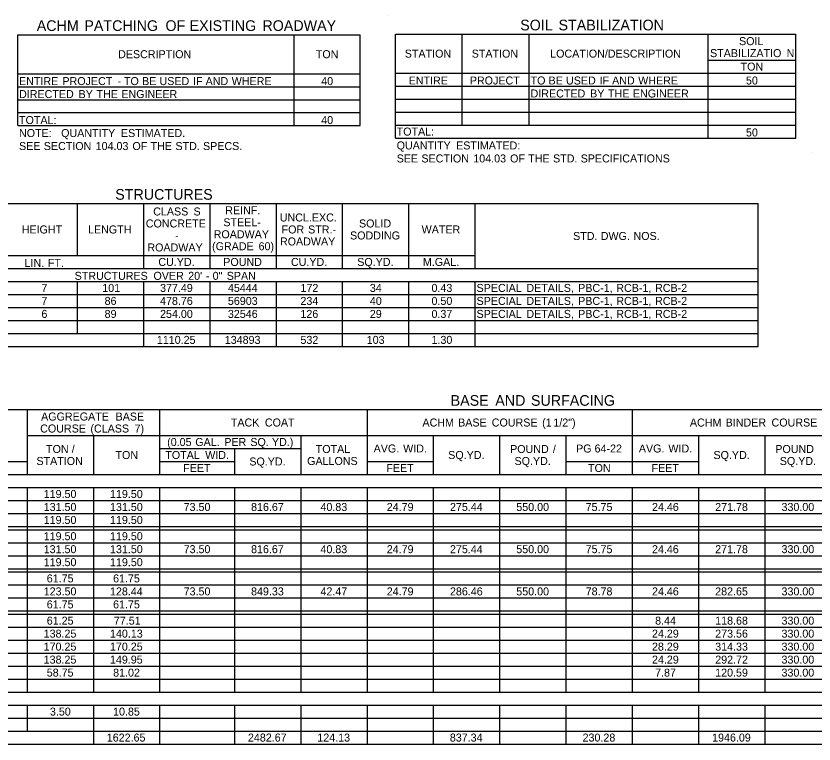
# Model space of a CAD drawing. Extents: x 1955554 to 1962042, y 565952 to 568347.
# Drawn here: x 1959025 to 1959623, y 566455 to 567002 of the extents above; entities that cross this region are included whole.
import ezdxf

# ---------------------------------------------------------------- set-up
doc = ezdxf.new("R2010")
doc.units = 0
doc.layers.add('Default', color=7, linetype='Continuous')

msp = doc.modelspace()

# ---------------------------------------------------------------- linework, layer by layer
at = {"layer": 'Default'}
for p, q in [((1959303.28, 567001.67), (1959303.28, 567001.67)), ((1959025.93, 566987.58), (1959282.84, 566987.58)), ((1959025.93, 566919.33), (1959025.93, 566987.58)), ((1959025.93, 566919.33), (1959025.93, 566987.58)), ((1959233.11, 566919.33), (1959233.11, 566987.58)), ((1959282.84, 566919.33), (1959282.84, 566987.58)), ((1959309.13, 566988.02), (1959609.43, 566988.02)), ((1959309.13, 566910.02), (1959309.13, 566988.02)), ((1959309.13, 566910.02), (1959309.13, 566988.02)), ((1959359.34, 566919.77), (1959359.34, 566988.02)), ((1959409.55, 566919.77), (1959409.55, 566988.02)), ((1959543.61, 566910.02), (1959543.61, 566988.02)), ((1959609.43, 566910.02), (1959609.43, 566988.02)), ((1959609.43, 566910.02), (1959609.43, 566988.02)), ((1959543.61, 566968.52), (1959609.43, 566968.52)), ((1959543.61, 566968.52), (1959609.43, 566968.52)), ((1959025.93, 566958.33), (1959282.84, 566958.33)), ((1959233.11, 566919.33), (1959233.11, 566958.33)), ((1959282.84, 566919.33), (1959282.84, 566958.33)), ((1959309.13, 566958.77), (1959609.43, 566958.77)), ((1959359.34, 566919.77), (1959359.34, 566958.77)), ((1959409.55, 566919.77), (1959409.55, 566958.77)), ((1959543.61, 566919.77), (1959543.61, 566958.77)), ((1959025.93, 566948.58), (1959282.84, 566948.58)), ((1959309.13, 566949.02), (1959609.43, 566949.02)), ((1959543.61, 566949.02), (1959609.43, 566949.02)), ((1959025.93, 566938.83), (1959282.84, 566938.83)), ((1959309.13, 566939.27), (1959609.43, 566939.27)), ((1959025.93, 566929.08), (1959282.84, 566929.08)), ((1959309.13, 566929.52), (1959609.43, 566929.52)), ((1959025.93, 566919.33), (1959282.84, 566919.33)), ((1959309.13, 566919.77), (1959609.43, 566919.77)), ((1959309.13, 566919.77), (1959609.43, 566919.77)), ((1959309.13, 566910.02), (1959609.43, 566910.02)), ((1959621.57, 566899.1), (1959621.57, 566899.1)), ((1958692.87, 566860.92), (1959581.1, 566860.92)), ((1959070.69, 566821.92), (1959070.69, 566860.92)), ((1959120.41, 566812.17), (1959120.41, 566860.92)), ((1959170.14, 566812.17), (1959170.14, 566860.92)), ((1959219.86, 566812.17), (1959219.86, 566860.92)), ((1959269.59, 566812.17), (1959269.59, 566860.92)), ((1959319.31, 566812.17), (1959319.31, 566860.92)), ((1959319.31, 566812.17), (1959319.31, 566860.92)), ((1959369.04, 566812.17), (1959369.04, 566860.92)), ((1959581.1, 566753.67), (1959581.1, 566860.92)), ((1958971.24, 566821.92), (1959369.04, 566821.92)), ((1959170.14, 566812.17), (1959170.14, 566821.92)), ((1959219.86, 566812.17), (1959219.86, 566821.92)), ((1959269.59, 566812.17), (1959269.59, 566821.92)), ((1959369.04, 566812.17), (1959369.04, 566821.92)), ((1958692.87, 566812.17), (1959581.1, 566812.17)), ((1959369.04, 566812.17), (1959581.1, 566812.17)), ((1959581.1, 566763.42), (1959581.1, 566812.17)), ((1958692.87, 566802.42), (1959581.1, 566802.42)), ((1959070.69, 566763.42), (1959070.69, 566802.42)), ((1959070.69, 566763.42), (1959070.69, 566802.42)), ((1959120.41, 566753.67), (1959120.41, 566802.42)), ((1959120.41, 566753.67), (1959120.41, 566802.42)), ((1959170.14, 566753.67), (1959170.14, 566802.42)), ((1959170.14, 566753.67), (1959170.14, 566802.42)), ((1959219.86, 566753.67), (1959219.86, 566802.42)), ((1959219.86, 566753.67), (1959219.86, 566802.42)), ((1959269.59, 566753.67), (1959269.59, 566802.42)), ((1959269.59, 566753.67), (1959269.59, 566802.42)), ((1959319.31, 566753.67), (1959319.31, 566802.42)), ((1959319.31, 566753.67), (1959319.31, 566802.42)), ((1959369.04, 566802.42), (1959581.1, 566802.42)), ((1959369.04, 566773.17), (1959369.04, 566802.42)), ((1959369.04, 566753.67), (1959369.04, 566802.42)), ((1958692.87, 566792.67), (1959581.1, 566792.67)), ((1958692.87, 566782.92), (1959581.1, 566782.92)), ((1958692.87, 566773.17), (1959581.1, 566773.17)), ((1958692.87, 566763.42), (1959369.04, 566763.42)), ((1958971.24, 566763.42), (1959369.04, 566763.42)), ((1959369.04, 566763.42), (1959581.1, 566763.42)), ((1959369.04, 566763.42), (1959581.1, 566763.42)), ((1958692.87, 566753.67), (1959581.1, 566753.67)), ((1958693.85, 566706.28), (1960133.43, 566706.28)), ((1959033.15, 566657.53), (1959033.15, 566706.28)), ((1959132.6, 566657.53), (1959132.6, 566706.28)), ((1959288.11, 566657.53), (1959288.11, 566706.28)), ((1959487.01, 566686.78), (1959487.01, 566706.28)), ((1959487.01, 566657.53), (1959487.01, 566706.28)), ((1959033.15, 566686.78), (1960133.43, 566686.78)), ((1959082.87, 566657.53), (1959082.87, 566686.78)), ((1959238.38, 566677.03), (1959238.38, 566686.78)), ((1959238.38, 566657.53), (1959238.38, 566686.78)), ((1959337.83, 566657.53), (1959337.83, 566686.78)), ((1959387.56, 566657.53), (1959387.56, 566686.78)), ((1959437.28, 566657.53), (1959437.28, 566686.78)), ((1959536.73, 566657.53), (1959536.73, 566686.78)), ((1959586.46, 566657.53), (1959586.46, 566686.78)), ((1959132.6, 566677.03), (1959238.38, 566677.03)), ((1959188.66, 566657.53), (1959188.66, 566677.03)), ((1958983.42, 566667.28), (1959033.15, 566667.28)), ((1959033.15, 566657.53), (1959033.15, 566667.28)), ((1959132.6, 566667.28), (1959188.66, 566667.28)), ((1959188.66, 566657.53), (1959188.66, 566667.28)), ((1959288.11, 566667.28), (1959337.83, 566667.28)), ((1959337.83, 566657.53), (1959337.83, 566667.28)), ((1959437.28, 566667.28), (1959536.73, 566667.28)), ((1959536.73, 566657.53), (1959536.73, 566667.28)), ((1958693.85, 566657.53), (1960133.43, 566657.53)), ((1959033.15, 566657.53), (1959188.66, 566657.53)), ((1959188.66, 566657.53), (1959337.83, 566657.53)), ((1959337.83, 566657.53), (1959536.73, 566657.53)), ((1959536.73, 566657.53), (1959735.63, 566657.53)), ((1958693.85, 566647.78), (1960133.43, 566647.78)), ((1959033.15, 566494.22), (1959033.15, 566647.78)), ((1959033.15, 566494.22), (1959033.15, 566647.78)), ((1959082.87, 566494.22), (1959082.87, 566647.78)), ((1959082.87, 566494.22), (1959082.87, 566647.78)), ((1959132.6, 566494.22), (1959132.6, 566647.78)), ((1959132.6, 566494.22), (1959132.6, 566647.78)), ((1959188.66, 566494.22), (1959188.66, 566647.78)), ((1959188.66, 566494.22), (1959188.66, 566647.78)), ((1959238.38, 566494.22), (1959238.38, 566647.78)), ((1959238.38, 566494.22), (1959238.38, 566647.78)), ((1959288.11, 566494.22), (1959288.11, 566647.78)), ((1959288.11, 566494.22), (1959288.11, 566647.78)), ((1959337.83, 566494.22), (1959337.83, 566647.78)), ((1959337.83, 566494.22), (1959337.83, 566647.78)), ((1959387.56, 566494.22), (1959387.56, 566647.78)), ((1959387.56, 566494.22), (1959387.56, 566647.78)), ((1959437.28, 566494.22), (1959437.28, 566647.78)), ((1959437.28, 566494.22), (1959437.28, 566647.78)), ((1959487.01, 566494.22), (1959487.01, 566647.78)), ((1959487.01, 566494.22), (1959487.01, 566647.78)), ((1959536.73, 566494.22), (1959536.73, 566647.78)), ((1959536.73, 566494.22), (1959536.73, 566647.78)), ((1959586.46, 566494.22), (1959586.46, 566647.78)), ((1959586.46, 566494.22), (1959586.46, 566647.78)), ((1958693.85, 566638.03), (1960133.43, 566638.03)), ((1958693.85, 566628.28), (1960133.43, 566628.28)), ((1958693.85, 566618.53), (1960133.43, 566618.53)), ((1958693.85, 566616.09), (1960133.43, 566616.09)), ((1958693.85, 566606.34), (1960133.43, 566606.34)), ((1958693.85, 566596.59), (1960133.43, 566596.59)), ((1958693.85, 566586.84), (1960133.43, 566586.84)), ((1958693.85, 566584.4), (1960133.43, 566584.4)), ((1958693.85, 566574.65), (1960133.43, 566574.65)), ((1958693.85, 566564.9), (1960133.43, 566564.9)), ((1958693.85, 566555.15), (1960133.43, 566555.15)), ((1958693.85, 566552.72), (1960133.43, 566552.72)), ((1958693.85, 566542.97), (1960133.43, 566542.97)), ((1958693.85, 566533.22), (1960133.43, 566533.22)), ((1958693.85, 566523.47), (1960133.43, 566523.47)), ((1958693.85, 566513.72), (1960133.43, 566513.72)), ((1958693.85, 566503.97), (1960133.43, 566503.97)), ((1958693.85, 566494.22), (1960133.43, 566494.22)), ((1958693.85, 566494.22), (1960133.43, 566494.22)), ((1958693.85, 566484.47), (1960133.43, 566484.47)), ((1959033.15, 566464.97), (1959033.15, 566484.47)), ((1959033.15, 566464.97), (1959033.15, 566484.47)), ((1959082.87, 566455.22), (1959082.87, 566484.47)), ((1959082.87, 566455.22), (1959082.87, 566484.47)), ((1959132.6, 566455.22), (1959132.6, 566484.47)), ((1959132.6, 566455.22), (1959132.6, 566484.47)), ((1959188.66, 566455.22), (1959188.66, 566484.47)), ((1959188.66, 566455.22), (1959188.66, 566484.47)), ((1959238.38, 566464.97), (1959238.38, 566484.47)), ((1959238.38, 566455.22), (1959238.38, 566484.47)), ((1959288.11, 566455.22), (1959288.11, 566484.47)), ((1959288.11, 566455.22), (1959288.11, 566484.47)), ((1959337.83, 566455.22), (1959337.83, 566484.47)), ((1959337.83, 566455.22), (1959337.83, 566484.47)), ((1959387.56, 566455.22), (1959387.56, 566484.47)), ((1959387.56, 566455.22), (1959387.56, 566484.47)), ((1959437.28, 566455.22), (1959437.28, 566484.47)), ((1959437.28, 566455.22), (1959437.28, 566484.47)), ((1959487.01, 566455.22), (1959487.01, 566484.47)), ((1959487.01, 566455.22), (1959487.01, 566484.47)), ((1959536.73, 566455.22), (1959536.73, 566484.47)), ((1959536.73, 566455.22), (1959536.73, 566484.47)), ((1959586.46, 566455.22), (1959586.46, 566484.47)), ((1959586.46, 566455.22), (1959586.46, 566484.47)), ((1958693.85, 566474.72), (1960133.43, 566474.72)), ((1958693.85, 566464.97), (1960133.43, 566464.97)), ((1958693.85, 566455.22), (1960133.43, 566455.22))]:
    msp.add_line(p, q, dxfattribs=at)

# ---------------------------------------------------------------- texts
for s, height, p in [('ACHM', 8, (1959040.2, 566990.41)), (' PATCHING', 8, (1959072.93, 566990.41)), (' OF', 8, (1959133.74, 566990.41)), (' EXISTING', 8, (1959151.85, 566990.41)), (' ROADWAY', 8, (1959206.45, 566990.41)), ('SOIL', 8, (1959402.76, 566990.84)), (' STABILIZATION', 8, (1959428.51, 566990.84)), ('SOIL', 6, (1959566.86, 566979.77)), ('DESCRIPTION', 6, (1959101.21, 566969.96)), ('TON', 6, (1959249.46, 566969.96)), ('STATION', 6, (1959316.17, 566970.39)), ('STATION', 6, (1959366.38, 566970.39)), ('LOCATION/DESCRIPTION', 6, (1959425.22, 566970.39)), ('STABILIZATIO', 6, (1959545.12, 566970.77)), ('N', 6, (1959602.54, 566970.77)), ('TON', 6, (1959568.01, 566960.64)), ('ENTIRE', 6, (1959026.9, 566949.78)), (' PROJECT', 6, (1959057.2, 566949.78)), (' TO', 6, (1959103.35, 566949.78)), (' BE', 6, (1959116.94, 566949.78)), (' USED', 6, (1959130.01, 566949.78)), (' IF', 6, (1959155.18, 566949.78)), (' AND', 6, (1959164.58, 566949.78)), (' WHERE', 6, (1959184.16, 566949.78)), ('40', 6, (1959253.52, 566949.78)), ('ENTIRE', 6, (1959319.08, 566950.22)), ('PROJECT', 6, (1959364.96, 566950.22)), ('TO', 6, (1959410.53, 566950.22)), (' BE', 6, (1959421.79, 566950.22)), (' USED', 6, (1959434.86, 566950.22)), (' IF', 6, (1959460.04, 566950.22)), (' AND', 6, (1959469.43, 566950.22)), (' WHERE', 6, (1959489.01, 566950.22)), ('50', 6, (1959572.06, 566950.22)), (' -', 6, (1959098.49, 566949.78)), ('DIRECTED', 6, (1959026.9, 566940.03)), (' BY', 6, (1959069.31, 566940.03)), (' THE', 6, (1959082.76, 566940.03)), (' ENGINEER', 6, (1959101.41, 566940.03)), ('DIRECTED', 6, (1959410.53, 566940.47)), (' BY', 6, (1959452.93, 566940.47)), (' THE', 6, (1959466.38, 566940.47)), (' ENGINEER', 6, (1959485.03, 566940.47)), ('TOTAL:', 6, (1959026.9, 566920.53)), ('40', 6, (1959253.52, 566920.53)), ('NOTE:', 6, (1959026.9, 566910.78)), ('   QUANTITY', 6, (1959051.79, 566910.78)), (' ESTIMATED.', 6, (1959101.1, 566910.78)), ('TOTAL:', 6, (1959310.1, 566911.89)), ('50', 6, (1959572.06, 566911.22)), ('SEE', 6, (1959026.9, 566901.03)), (' SECTION', 6, (1959043.23, 566901.03)), (' 104.03', 6, (1959082.14, 566901.03)), (' OF', 6, (1959109.72, 566901.03)), (' THE', 6, (1959123.3, 566901.03)), (' STD.', 6, (1959141.95, 566901.03)), (' SPECS.', 6, (1959162.65, 566901.03)), ('QUANTITY', 6, (1959310.1, 566901.47)), (' ESTIMATED:', 6, (1959352.43, 566901.47)), ('SEE', 6, (1959310.1, 566891.72)), (' SECTION', 6, (1959326.43, 566891.72)), (' 104.03', 6, (1959365.34, 566891.72)), (' OF', 6, (1959392.92, 566891.72)), (' THE', 6, (1959406.5, 566891.72)), (' STD.', 6, (1959425.15, 566891.72)), (' SPECIFICATIONS', 6, (1959445.85, 566891.72)), ('STRUCTURES', 8, (1959099.06, 566863.74)), ('CLASS', 6, (1959127.52, 566851.92)), (' S', 6, (1959155.52, 566851.92)), ('REINF.', 6, (1959181.55, 566852.82)), ('CONCRETE', 6, (1959121.96, 566842.92)), ('STEEL-', 6, (1959180.12, 566843.82)), ('UNCL.EXC.', 6, (1959222.42, 566847.42)), ('SOLID', 6, (1959281.85, 566842.92)), ('HEIGHT', 6, (1959028.91, 566838.42)), ('LENGTH', 6, (1959078.64, 566838.42)), ('FOR', 6, (1959223.82, 566838.42)), (' STR.-', 6, (1959241.47, 566838.42)), ('WATER', 6, (1959328.83, 566838.42)), ('-', 6, (1959143.91, 566833.92)), ('ROADWAY', 6, (1959172.87, 566834.82)), ('SODDING', 6, (1959275.14, 566833.92)), ('STD.', 6, (1959442.4, 566833.54)), (' DWG.', 6, (1959460.92, 566833.54)), (' NOS.', 6, (1959485.49, 566833.54)), ('ROADWAY', 6, (1959123.14, 566824.92)), ('(GRADE', 6, (1959171.67, 566825.82)), (' 60)', 6, (1959204.32, 566825.82)), ('ROADWAY', 6, (1959222.59, 566829.42)), ('LIN.', 6, (1959031.03, 566813.37)), (' FT.', 6, (1959046.29, 566813.37)), ('CU.YD.', 6, (1959131.36, 566814.04)), ('POUND', 6, (1959180.07, 566814.04)), ('CU.YD.', 6, (1959230.81, 566814.04)), ('SQ.YD.', 6, (1959280.53, 566814.04)), ('M.GAL.', 6, (1959329.79, 566814.04)), ('STRUCTURES', 6, (1959068.6, 566803.62)), (' OVER', 6, (1959125.49, 566803.62)), (" 20'", 6, (1959151.54, 566803.62)), (' -', 6, (1959164.81, 566803.62)), (' 0"', 6, (1959169.87, 566803.62)), (' SPAN', 6, (1959180.42, 566803.62)), ('7', 6, (1959043.68, 566794.54)), ('101', 6, (1959089.33, 566794.54)), ('377.49', 6, (1959132.65, 566794.54)), ('45444', 6, (1959183.55, 566794.54)), ('172', 6, (1959237.96, 566794.54)), ('34', 6, (1959289.99, 566794.54)), ('0.43', 6, (1959336.21, 566794.54)), ('SPECIAL', 6, (1959370.01, 566794.54)), (' DETAILS,', 6, (1959405.13, 566794.54)), (' PBC-1,', 6, (1959443.98, 566794.54)), (' RCB-1,', 6, (1959472.58, 566794.54)), (' RCB-2', 6, (1959501.65, 566794.54)), ('7', 6, (1959043.68, 566784.79)), ('86', 6, (1959091.08, 566784.79)), ('478.76', 6, (1959132.65, 566784.79)), ('56903', 6, (1959183.54, 566784.79)), ('234', 6, (1959237.94, 566784.79)), ('40', 6, (1959289.99, 566784.79)), ('0.50', 6, (1959336.22, 566784.79)), ('SPECIAL', 6, (1959370.01, 566784.79)), (' DETAILS,', 6, (1959405.13, 566784.79)), (' PBC-1,', 6, (1959443.98, 566784.79)), (' RCB-1,', 6, (1959472.58, 566784.79)), (' RCB-2', 6, (1959501.65, 566784.79)), ('6', 6, (1959043.68, 566775.04)), ('89', 6, (1959091.07, 566775.04)), ('254.00', 6, (1959132.66, 566775.04)), ('32546', 6, (1959183.54, 566775.04)), ('126', 6, (1959237.92, 566775.04)), ('29', 6, (1959289.97, 566775.04)), ('0.37', 6, (1959336.21, 566775.04)), ('SPECIAL', 6, (1959370.01, 566775.04)), (' DETAILS,', 6, (1959405.13, 566775.04)), (' PBC-1,', 6, (1959443.98, 566775.04)), (' RCB-1,', 6, (1959472.58, 566775.04)), (' RCB-2', 6, (1959501.65, 566775.04)), ('1110.25', 6, (1959130.26, 566755.54)), ('134893', 6, (1959181.2, 566755.54)), ('532', 6, (1959237.94, 566755.54)), ('103', 6, (1959287.64, 566755.54)), ('1.30', 6, (1959336.23, 566755.54)), ('BASE', 8, (1959350.56, 566709.1)), (' AND', 8, (1959381.07, 566709.1)), (' SURFACING', 8, (1959407.84, 566709.1)), ('AGGREGATE', 6, (1959043.46, 566698.03)), (' BASE', 6, (1959097.08, 566698.03)), ('TACK', 6, (1959185.76, 566693.53)), (' COAT', 6, (1959209.03, 566693.53)), ('ACHM', 6, (1959329.43, 566693.53)), (' BASE', 6, (1959353.97, 566693.53)), (' COURSE', 6, (1959379.18, 566693.53)), (' (1', 6, (1959416.97, 566693.53)), (' 1/2")', 6, (1959425.38, 566693.53)), ('ACHM', 6, (1959530.02, 566693.53)), (' BINDER', 6, (1959554.57, 566693.53)), (' COURSE', 6, (1959589, 566693.53)), ('COURSE', 6, (1959042.75, 566689.03)), (' (CLASS', 6, (1959078.2, 566689.03)), (' 7)', 6, (1959111.32, 566689.03)), ('(0.05', 6, (1959137.99, 566678.9)), (' GAL.', 6, (1959156.83, 566678.9)), (' PER', 6, (1959178.61, 566678.9)), (' SQ.', 6, (1959198.14, 566678.9)), (' YD.)', 6, (1959214.33, 566678.9)), ('TON', 6, (1959047.16, 566673.65)), (' /', 6, (1959064.19, 566673.65)), ('TON', 6, (1959099.22, 566669.15)), ('TOTAL', 6, (1959136.59, 566669.15)), (' WID.', 6, (1959164.29, 566669.15)), ('TOTAL', 6, (1959249.4, 566673.65)), ('AVG.', 6, (1959292.82, 566674.03)), (' WID.', 6, (1959312.74, 566674.03)), ('SQ.YD.', 6, (1959348.77, 566669.15)), ('POUND', 6, (1959395.16, 566673.65)), (' /', 6, (1959425.02, 566673.65)), ('PG', 6, (1959444.67, 566674.03)), (' 64-22', 6, (1959456.28, 566674.03)), ('AVG.', 6, (1959491.72, 566674.03)), (' WID.', 6, (1959511.64, 566674.03)), ('SQ.YD.', 6, (1959547.67, 566669.15)), ('POUND', 6, (1959594.06, 566673.65)), ('STATION', 6, (1959039.95, 566664.65)), ('SQ.YD.', 6, (1959199.6, 566664.28)), ('GALLONS', 6, (1959242.96, 566664.65)), ('SQ.YD.', 6, (1959398.5, 566664.65)), ('SQ.YD.', 6, (1959597.4, 566664.65)), ('FEET', 6, (1959150, 566659.4)), ('FEET', 6, (1959302.34, 566659.4)), ('TON', 6, (1959453.63, 566659.4)), ('FEET', 6, (1959501.24, 566659.4)), ('119.50', 6, (1959045.39, 566639.9)), ('119.50', 6, (1959095.12, 566639.9)), ('131.50', 6, (1959045.39, 566630.15)), ('131.50', 6, (1959095.12, 566630.15)), ('73.50', 6, (1959150.34, 566630.15)), ('816.67', 6, (1959200.9, 566630.15)), ('40.83', 6, (1959252.95, 566630.15)), ('24.79', 6, (1959302.67, 566630.15)), ('275.44', 6, (1959350.08, 566630.15)), ('550.00', 6, (1959399.81, 566630.15)), ('75.75', 6, (1959451.83, 566630.15)), ('24.46', 6, (1959501.58, 566630.15)), ('271.78', 6, (1959548.97, 566630.15)), ('330.00', 6, (1959598.71, 566630.15)), ('119.50', 6, (1959045.39, 566620.4)), ('119.50', 6, (1959095.12, 566620.4)), ('119.50', 6, (1959045.39, 566608.22)), ('119.50', 6, (1959095.12, 566608.22)), ('131.50', 6, (1959045.39, 566598.47)), ('131.50', 6, (1959095.12, 566598.47)), ('73.50', 6, (1959150.34, 566598.47)), ('816.67', 6, (1959200.9, 566598.47)), ('40.83', 6, (1959252.95, 566598.47)), ('24.79', 6, (1959302.67, 566598.47)), ('275.44', 6, (1959350.08, 566598.47)), ('550.00', 6, (1959399.81, 566598.47)), ('75.75', 6, (1959451.83, 566598.47)), ('24.46', 6, (1959501.58, 566598.47)), ('271.78', 6, (1959548.97, 566598.47)), ('330.00', 6, (1959598.71, 566598.47)), ('119.50', 6, (1959045.39, 566588.72)), ('119.50', 6, (1959095.12, 566588.72)), ('61.75', 6, (1959047.69, 566576.53)), ('61.75', 6, (1959097.42, 566576.53)), ('123.50', 6, (1959045.39, 566566.78)), ('128.44', 6, (1959095.12, 566566.78)), ('73.50', 6, (1959150.34, 566566.78)), ('849.33', 6, (1959200.9, 566566.78)), ('42.47', 6, (1959252.95, 566566.78)), ('24.79', 6, (1959302.67, 566566.78)), ('286.46', 6, (1959350.07, 566566.78)), ('550.00', 6, (1959399.81, 566566.78)), ('78.78', 6, (1959451.85, 566566.78)), ('24.46', 6, (1959501.58, 566566.78)), ('282.65', 6, (1959548.95, 566566.78)), ('330.00', 6, (1959598.71, 566566.78)), ('61.75', 6, (1959047.69, 566557.03)), ('61.75', 6, (1959097.42, 566557.03)), ('61.25', 6, (1959047.69, 566544.84)), ('77.51', 6, (1959098.02, 566544.84)), ('8.44', 6, (1959503.92, 566544.84)), ('118.68', 6, (1959548.97, 566544.84)), ('330.00', 6, (1959598.71, 566544.84)), ('138.25', 6, (1959045.36, 566535.09)), ('140.13', 6, (1959095.11, 566535.09)), ('24.29', 6, (1959501.57, 566535.09)), ('273.56', 6, (1959548.97, 566535.09)), ('330.00', 6, (1959598.71, 566535.09)), ('170.25', 6, (1959045.36, 566525.34)), ('170.25', 6, (1959095.09, 566525.34)), ('28.29', 6, (1959501.57, 566525.34)), ('314.33', 6, (1959548.97, 566525.34)), ('330.00', 6, (1959598.71, 566525.34)), ('138.25', 6, (1959045.36, 566515.59)), ('149.95', 6, (1959095.09, 566515.59)), ('24.29', 6, (1959501.57, 566515.59)), ('292.72', 6, (1959549, 566515.59)), ('330.00', 6, (1959598.71, 566515.59)), ('58.75', 6, (1959047.69, 566505.84)), ('81.02', 6, (1959097.47, 566505.84)), ('7.87', 6, (1959503.91, 566505.84)), ('120.59', 6, (1959548.97, 566505.84)), ('330.00', 6, (1959598.71, 566505.84)), ('3.50', 6, (1959050.06, 566476.59)), ('10.85', 6, (1959097.42, 566476.59)), ('1622.65', 6, (1959092.71, 566457.09)), ('2482.67', 6, (1959198.56, 566457.09)), ('124.13', 6, (1959250.61, 566457.09)), ('837.34', 6, (1959349.98, 566457.09)), ('230.28', 6, (1959449.52, 566457.09)), ('1946.09', 6, (1959546.65, 566457.09))]:
    msp.add_text(s, height=height, dxfattribs=at).set_placement(p)

doc.saveas('drawing.dxf')
